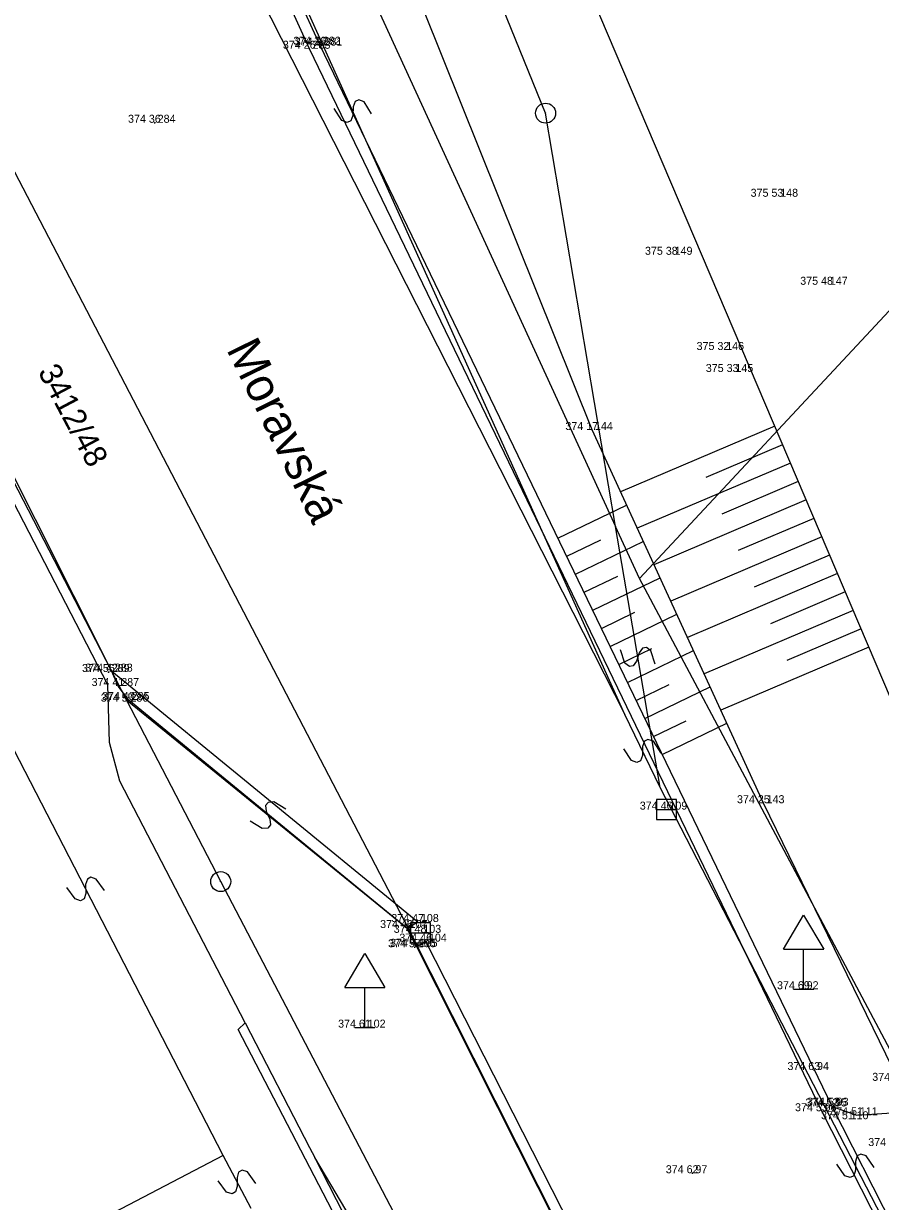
# Model space of a CAD drawing. Extents: x -601196 to -600262, y -1082523 to -1081922.
# Drawn here: x -600485.65 to -600464.23, y -1082316.78 to -1082287.34 of the extents above; entities that cross this region are included whole.
import ezdxf

# ---------------------------------------------------------------- set-up
doc = ezdxf.new("R2010")
doc.units = 0
for name, color, linetype in [('Vrstva 1', 7, 'Continuous'), ('Vrstva 10', 7, 'Continuous'), ('Vrstva 11', 7, 'Continuous'), ('Vrstva 14', 7, 'Continuous'), ('Vrstva 2', 7, 'Continuous'), ('Vrstva 20', 7, 'Continuous'), ('Vrstva 25', 7, 'Continuous'), ('Vrstva 27', 7, 'Continuous'), ('Vrstva 3', 7, 'Continuous'), ('Vrstva 34', 7, 'Continuous'), ('Vrstva 47', 7, 'Continuous')]:
    doc.layers.add(name, color=color, linetype=linetype)

msp = doc.modelspace()

# ---------------------------------------------------------------- linework, layer by layer
at = {"layer": 'Vrstva 1'}
for p, q in [((-600478.5, -1082287.97), (-600478.5, -1082287.97)), ((-600478.24, -1082287.87), (-600478.24, -1082287.87)), ((-600478.2, -1082287.89), (-600478.2, -1082287.89)), ((-600482.37, -1082289.82), (-600482.37, -1082289.82)), ((-600466.81, -1082291.67), (-600466.81, -1082291.67)), ((-600469.45, -1082293.12), (-600469.45, -1082293.12)), ((-600465.57, -1082293.87), (-600465.57, -1082293.87)), ((-600468.16, -1082295.5), (-600468.16, -1082295.5)), ((-600467.93, -1082296.05), (-600467.93, -1082296.05)), ((-600471.44, -1082297.5), (-600471.44, -1082297.5)), ((-600483.52, -1082303.55), (-600483.52, -1082303.55)), ((-600483.44, -1082303.54), (-600483.44, -1082303.54)), ((-600483.28, -1082303.9), (-600483.28, -1082303.9)), ((-600483.02, -1082304.25), (-600483.02, -1082304.25)), ((-600483.05, -1082304.29), (-600483.05, -1082304.29)), ((-600467.15, -1082306.83), (-600467.15, -1082306.83)), ((-600469.58, -1082306.99), (-600469.58, -1082306.99)), ((-600475.79, -1082309.8), (-600475.79, -1082309.8)), ((-600476.07, -1082309.95), (-600476.07, -1082309.95)), ((-600475.73, -1082310.07), (-600475.73, -1082310.07)), ((-600475.87, -1082310.43), (-600475.87, -1082310.43)), ((-600475.82, -1082310.42), (-600475.82, -1082310.42)), ((-600475.59, -1082310.29), (-600475.59, -1082310.29)), ((-600466.15, -1082311.48), (-600466.15, -1082311.48)), ((-600477.12, -1082312.44), (-600477.12, -1082312.44)), ((-600465.89, -1082313.5), (-600465.89, -1082313.5)), ((-600465.7, -1082314.53), (-600465.7, -1082314.53)), ((-600465.44, -1082314.41), (-600465.44, -1082314.41)), ((-600465.4, -1082314.39), (-600465.4, -1082314.39)), ((-600465.05, -1082314.73), (-600465.05, -1082314.73)), ((-600464.82, -1082314.63), (-600464.82, -1082314.63)), ((-600468.93, -1082316.08), (-600468.93, -1082316.08))]:
    msp.add_line(p, q, dxfattribs=at)
at = {"layer": 'Vrstva 10'}
for p, q in [((-600478.24, -1082287.87), (-600482.87, -1082277.7)), ((-600465.44, -1082314.41), (-600478.24, -1082287.87)), ((-600483.44, -1082303.54), (-600486.56, -1082297.33)), ((-600483.28, -1082303.9), (-600483.44, -1082303.54)), ((-600483.02, -1082304.25), (-600483.28, -1082303.9)), ((-600476.07, -1082309.95), (-600483.02, -1082304.25)), ((-600475.82, -1082310.42), (-600476.07, -1082309.95)), ((-600472.22, -1082317.55), (-600475.82, -1082310.42)), ((-600460.01, -1082325.09), (-600465.44, -1082314.41))]:
    msp.add_line(p, q, dxfattribs=at)
at = {"layer": 'Vrstva 11'}
for p, q in [((-600478.5, -1082287.97), (-600483.06, -1082277.86)), ((-600465.7, -1082314.53), (-600478.5, -1082287.97)), ((-600475.79, -1082309.8), (-600483.44, -1082303.54)), ((-600476.07, -1082309.95), (-600475.79, -1082309.8)), ((-600475.59, -1082310.29), (-600475.82, -1082310.42)), ((-600471.95, -1082317.45), (-600475.59, -1082310.29)), ((-600460.25, -1082325.17), (-600465.7, -1082314.53)), ((-600465.44, -1082314.41), (-600464.82, -1082314.63)), ((-600464.82, -1082314.63), (-600462.97, -1082314.5))]:
    msp.add_line(p, q, dxfattribs=at)
at = {"layer": 'Vrstva 14'}
for p, q in [((-600463.33, -1082305.73), (-600472.01, -1082285.33)), ((-600471.44, -1082297.5), (-600475.64, -1082287.01)), ((-600467.15, -1082306.83), (-600471.44, -1082297.5)), ((-600463.77, -1082313.77), (-600467.15, -1082306.83))]:
    msp.add_line(p, q, dxfattribs=at)
at = {"layer": 'Vrstva 20'}
for p, q in [((-600478.21, -1082287.89), (-600478.19, -1082287.89)), ((-600478.2, -1082287.875), (-600478.2, -1082287.89)), ((-600478.2, -1082287.905), (-600478.2, -1082287.89)), ((-600482.38, -1082289.82), (-600482.36, -1082289.82)), ((-600482.37, -1082289.805), (-600482.37, -1082289.82)), ((-600482.37, -1082289.835), (-600482.37, -1082289.82)), ((-600483.53, -1082303.55), (-600483.51, -1082303.55)), ((-600483.52, -1082303.535), (-600483.52, -1082303.55)), ((-600483.52, -1082303.565), (-600483.52, -1082303.55)), ((-600483.06, -1082304.29), (-600483.04, -1082304.29)), ((-600483.05, -1082304.275), (-600483.05, -1082304.29)), ((-600483.05, -1082304.305), (-600483.05, -1082304.29)), ((-600475.88, -1082310.43), (-600475.86, -1082310.43)), ((-600475.87, -1082310.415), (-600475.87, -1082310.43)), ((-600475.87, -1082310.445), (-600475.87, -1082310.43)), ((-600465.9, -1082313.5), (-600465.88, -1082313.5)), ((-600465.89, -1082313.485), (-600465.89, -1082313.5)), ((-600465.89, -1082313.515), (-600465.89, -1082313.5)), ((-600465.41, -1082314.39), (-600465.39, -1082314.39)), ((-600465.4, -1082314.375), (-600465.4, -1082314.39)), ((-600465.4, -1082314.405), (-600465.4, -1082314.39)), ((-600468.94, -1082316.08), (-600468.92, -1082316.08)), ((-600468.93, -1082316.065), (-600468.93, -1082316.08)), ((-600468.93, -1082316.095), (-600468.93, -1082316.08))]:
    msp.add_line(p, q, dxfattribs=at)
at = {"layer": 'Vrstva 25'}
for p, q in [((-600466.871, -1082297.408), (-600470.728, -1082299.049)), ((-600466.675, -1082297.868), (-600468.597, -1082298.686)), ((-600466.479, -1082298.328), (-600470.31, -1082299.958)), ((-600466.284, -1082298.788), (-600468.192, -1082299.601)), ((-600466.088, -1082299.249), (-600469.892, -1082300.867)), ((-600472.29, -1082300.207), (-600470.575, -1082299.38)), ((-600465.892, -1082299.709), (-600467.787, -1082300.515)), ((-600472.073, -1082300.657), (-600471.22, -1082300.246)), ((-600471.856, -1082301.108), (-600470.158, -1082300.289)), ((-600465.696, -1082300.169), (-600469.474, -1082301.776)), ((-600465.501, -1082300.629), (-600467.383, -1082301.43)), ((-600471.638, -1082301.558), (-600470.794, -1082301.151)), ((-600471.421, -1082302.008), (-600469.74, -1082301.198)), ((-600465.305, -1082301.089), (-600469.056, -1082302.685)), ((-600465.109, -1082301.549), (-600466.978, -1082302.344)), ((-600471.204, -1082302.459), (-600470.367, -1082302.055)), ((-600470.987, -1082302.909), (-600469.322, -1082302.106)), ((-600464.913, -1082302.009), (-600468.638, -1082303.594)), ((-600464.717, -1082302.469), (-600466.573, -1082303.259)), ((-600470.77, -1082303.359), (-600469.941, -1082302.96)), ((-600470.552, -1082303.81), (-600468.904, -1082303.015)), ((-600464.522, -1082302.929), (-600468.22, -1082304.503)), ((-600470.335, -1082304.26), (-600469.515, -1082303.865)), ((-600470.118, -1082304.71), (-600468.486, -1082303.924)), ((-600469.901, -1082305.161), (-600469.089, -1082304.769)), ((-600469.684, -1082305.611), (-600468.069, -1082304.832))]:
    msp.add_line(p, q, dxfattribs=at)
at = {"layer": 'Vrstva 27'}
for p, q in [((-600469.83, -1082306.99), (-600469.33, -1082306.99)), ((-600475.98, -1082310.07), (-600475.48, -1082310.07))]:
    msp.add_line(p, q, dxfattribs=at)
for points in [[(-600469.83, -1082307.24), (-600469.33, -1082307.24), (-600469.33, -1082306.74), (-600469.83, -1082306.74)], [(-600475.98, -1082310.32), (-600475.48, -1082310.32), (-600475.48, -1082309.82), (-600475.98, -1082309.82)]]:
    msp.add_lwpolyline(points, close=True, dxfattribs=at)
at = {"layer": 'Vrstva 34'}
for p, q in [((-600466.65, -1082310.48), (-600466.15, -1082309.63)), ((-600466.15, -1082309.63), (-600465.65, -1082310.48)), ((-600477.62, -1082311.44), (-600477.12, -1082310.59)), ((-600477.12, -1082310.59), (-600476.62, -1082311.44)), ((-600466.65, -1082310.48), (-600465.65, -1082310.48)), ((-600466.15, -1082311.48), (-600466.15, -1082310.48)), ((-600477.62, -1082311.44), (-600476.62, -1082311.44)), ((-600477.12, -1082312.44), (-600477.12, -1082311.44)), ((-600466.4, -1082311.48), (-600465.9, -1082311.48)), ((-600477.37, -1082312.44), (-600476.87, -1082312.44))]:
    msp.add_line(p, q, dxfattribs=at)
at = {"layer": 'Vrstva 47'}
for p, q in [((-600509.18, -1082228.7), (-600470.62, -1082304.61)), ((-600496.18, -1082271.26), (-600476.01, -1082310)), ((-600470.62, -1082304.61), (-600484.21, -1082274.45)), ((-600472.6, -1082289.58), (-600475.82, -1082281.64)), ((-600477.94, -1082284.47), (-600470.85, -1082299.91)), ((-600483.07, -1082304.26), (-600493.08, -1082284.9)), ((-600483.54, -1082303.87), (-600492.72, -1082286.11)), ((-600477.269, -1082289.244), (-600477.36, -1082289.286)), ((-600477.136, -1082289.295), (-600477.269, -1082289.244)), ((-600477.693, -1082289.764), (-600477.882, -1082289.466)), ((-600477.41, -1082289.418), (-600477.419, -1082289.641)), ((-600477.36, -1082289.286), (-600477.41, -1082289.418)), ((-600476.947, -1082289.593), (-600477.136, -1082289.295)), ((-600477.56, -1082289.815), (-600477.693, -1082289.764)), ((-600477.469, -1082289.773), (-600477.56, -1082289.815)), ((-600477.419, -1082289.641), (-600477.469, -1082289.773)), ((-600470.85, -1082299.91), (-600472.6, -1082289.58)), ((-600470.25, -1082301.21), (-600463.9, -1082294.4)), ((-600469.74, -1082306.44), (-600470.85, -1082299.91)), ((-600470.25, -1082301.21), (-600470.85, -1082299.91)), ((-600458.32, -1082323.68), (-600470.25, -1082301.21)), ((-600480.66, -1082315.64), (-600487.53, -1082302.31)), ((-600470.623, -1082303.332), (-600470.731, -1082302.995)), ((-600470.262, -1082303.068), (-600470.327, -1082303.281)), ((-600470.18, -1082302.952), (-600470.262, -1082303.068)), ((-600470.082, -1082302.935), (-600470.18, -1082302.952)), ((-600469.966, -1082303.017), (-600470.082, -1082302.935)), ((-600469.858, -1082303.354), (-600469.966, -1082303.017)), ((-600470.507, -1082303.414), (-600470.623, -1082303.332)), ((-600470.327, -1082303.281), (-600470.409, -1082303.397)), ((-600470.409, -1082303.397), (-600470.507, -1082303.414)), ((-600483.5, -1082305.31), (-600483.54, -1082303.87)), ((-600476.01, -1082310), (-600483.07, -1082304.26)), ((-600480.72, -1082308.79), (-600483.07, -1082304.26)), ((-600469.74, -1082306.44), (-600470.62, -1082304.61)), ((-600483.24, -1082306.28), (-600483.5, -1082305.31)), ((-600470.178, -1082305.413), (-600470.181, -1082305.636)), ((-600470.131, -1082305.279), (-600470.178, -1082305.413)), ((-600470.041, -1082305.236), (-600470.131, -1082305.279)), ((-600469.907, -1082305.283), (-600470.041, -1082305.236)), ((-600469.711, -1082305.576), (-600469.907, -1082305.283)), ((-600470.452, -1082305.766), (-600470.648, -1082305.473)), ((-600470.181, -1082305.636), (-600470.228, -1082305.77)), ((-600470.318, -1082305.813), (-600470.452, -1082305.766)), ((-600470.228, -1082305.77), (-600470.318, -1082305.813)), ((-600480.11, -1082312.32), (-600483.24, -1082306.28)), ((-600459.97, -1082325.35), (-600469.74, -1082306.44)), ((-600479.537, -1082306.809), (-600479.6, -1082306.887)), ((-600479.6, -1082306.887), (-600479.586, -1082307.028)), ((-600479.396, -1082306.795), (-600479.537, -1082306.809)), ((-600479.093, -1082306.977), (-600479.396, -1082306.795)), ((-600479.586, -1082307.028), (-600479.493, -1082307.231)), ((-600479.683, -1082307.464), (-600479.986, -1082307.282)), ((-600479.542, -1082307.45), (-600479.683, -1082307.464)), ((-600479.479, -1082307.372), (-600479.542, -1082307.45)), ((-600479.493, -1082307.231), (-600479.479, -1082307.372)), ((-600483.964, -1082308.682), (-600484.053, -1082308.728)), ((-600483.829, -1082308.725), (-600483.964, -1082308.682)), ((-600484.36, -1082309.224), (-600484.565, -1082308.936)), ((-600484.053, -1082308.728), (-600484.096, -1082308.863)), ((-600484.096, -1082308.863), (-600484.093, -1082309.086)), ((-600483.624, -1082309.013), (-600483.829, -1082308.725)), ((-600468.05, -1082332.99), (-600480.72, -1082308.79)), ((-600484.225, -1082309.267), (-600484.36, -1082309.224)), ((-600484.136, -1082309.221), (-600484.225, -1082309.267)), ((-600484.093, -1082309.086), (-600484.136, -1082309.221)), ((-600476.01, -1082310), (-600469.24, -1082323.45)), ((-600480.28, -1082312.49), (-600480.11, -1082312.32)), ((-600458.72, -1082354.01), (-600480.28, -1082312.49)), ((-600480.11, -1082312.32), (-600478.5, -1082315.44)), ((-600478.5, -1082315.44), (-600478.37, -1082315.69)), ((-600480.66, -1082315.64), (-600484.27, -1082317.52)), ((-600479.96, -1082316.96), (-600480.66, -1082315.64)), ((-600468.28, -1082335.2), (-600478.37, -1082315.69)), ((-600468.05, -1082332.99), (-600478.37, -1082315.69)), ((-600464.813, -1082315.648), (-600464.856, -1082315.783)), ((-600464.724, -1082315.602), (-600464.813, -1082315.648)), ((-600464.589, -1082315.645), (-600464.724, -1082315.602)), ((-600464.384, -1082315.933), (-600464.589, -1082315.645)), ((-600480.182, -1082316.006), (-600480.271, -1082316.053)), ((-600480.047, -1082316.047), (-600480.182, -1082316.006)), ((-600479.839, -1082316.333), (-600480.047, -1082316.047)), ((-600465.12, -1082316.144), (-600465.325, -1082315.856)), ((-600464.853, -1082316.006), (-600464.896, -1082316.141)), ((-600464.856, -1082315.783), (-600464.853, -1082316.006)), ((-600480.572, -1082316.552), (-600480.78, -1082316.266)), ((-600480.271, -1082316.053), (-600480.312, -1082316.188)), ((-600480.312, -1082316.188), (-600480.307, -1082316.411)), ((-600464.985, -1082316.187), (-600465.12, -1082316.144)), ((-600464.896, -1082316.141), (-600464.985, -1082316.187)), ((-600480.437, -1082316.593), (-600480.572, -1082316.552)), ((-600480.348, -1082316.546), (-600480.437, -1082316.593)), ((-600480.307, -1082316.411), (-600480.348, -1082316.546))]:
    msp.add_line(p, q, dxfattribs=at)
for centre, radius in [((-600472.6, -1082289.58), 0.25), ((-600472.6, -1082289.58), 0.005), ((-600480.72, -1082308.79), 0.25), ((-600480.72, -1082308.79), 0.005)]:
    msp.add_circle(centre, radius, dxfattribs=at)

# ---------------------------------------------------------------- texts
at = {"layer": 'Vrstva 2'}
for s, p in [(' 283', (-600478.5, -1082287.97)), (' 282', (-600478.24, -1082287.87)), (' 281', (-600478.2, -1082287.89)), (' 284', (-600482.37, -1082289.82)), (' 148', (-600466.81, -1082291.67)), (' 149', (-600469.45, -1082293.12)), (' 147', (-600465.57, -1082293.87)), (' 146', (-600468.16, -1082295.5)), (' 145', (-600467.93, -1082296.05)), (' 144', (-600471.44, -1082297.5)), (' 289', (-600483.52, -1082303.55)), (' 288', (-600483.44, -1082303.54)), (' 287', (-600483.28, -1082303.9)), (' 286', (-600483.05, -1082304.29)), (' 285', (-600483.02, -1082304.25)), (' 109', (-600469.58, -1082306.99)), (' 143', (-600467.15, -1082306.83)), (' 107', (-600476.07, -1082309.95)), (' 108', (-600475.79, -1082309.8)), (' 103', (-600475.73, -1082310.07)), (' 104', (-600475.59, -1082310.29)), (' 106', (-600475.87, -1082310.43)), (' 105', (-600475.82, -1082310.42)), (' 92', (-600466.15, -1082311.48)), (' 102', (-600477.12, -1082312.44)), (' 94', (-600465.89, -1082313.5)), (' 95', (-600465.44, -1082314.41)), (' 93', (-600465.4, -1082314.39)), (' 96', (-600465.7, -1082314.53)), (' 110', (-600465.05, -1082314.73)), (' 111', (-600464.82, -1082314.63)), (' 97', (-600468.93, -1082316.08))]:
    msp.add_text(s, height=0.2, dxfattribs=at).set_placement(p)
at = {"layer": 'Vrstva 3'}
for s, p in [('374 26 ', (-600479.166, -1082287.97)), ('374 26 ', (-600478.906, -1082287.87)), ('374 37 ', (-600478.866, -1082287.89)), ('374 36 ', (-600483.036, -1082289.82)), ('375 53 ', (-600467.476, -1082291.67)), ('375 38 ', (-600470.116, -1082293.12)), ('375 48 ', (-600466.236, -1082293.87)), ('375 32 ', (-600468.826, -1082295.5)), ('375 33 ', (-600468.596, -1082296.05)), ('374 17 ', (-600472.106, -1082297.5)), ('374 56 ', (-600484.186, -1082303.55)), ('374 42 ', (-600484.106, -1082303.54)), ('374 41 ', (-600483.946, -1082303.9)), ('374 55 ', (-600483.716, -1082304.29)), ('374 43 ', (-600483.686, -1082304.25)), ('374 46 ', (-600470.246, -1082306.99)), ('374 25 ', (-600467.816, -1082306.83)), ('374 46 ', (-600476.736, -1082309.95)), ('374 47 ', (-600476.456, -1082309.8)), ('374 48 ', (-600476.396, -1082310.07)), ('374 46 ', (-600476.256, -1082310.29)), ('374 57 ', (-600476.536, -1082310.43)), ('374 44 ', (-600476.486, -1082310.42)), ('374 69 ', (-600466.816, -1082311.48)), ('374 61 ', (-600477.786, -1082312.44)), ('374 63 ', (-600466.556, -1082313.5)), ('374 31 ', (-600464.436, -1082313.77)), ('374 52 ', (-600466.106, -1082314.41)), ('374 53 ', (-600466.066, -1082314.39)), ('374 53 ', (-600466.366, -1082314.53)), ('374 51 ', (-600465.716, -1082314.73)), ('374 51 ', (-600465.486, -1082314.63)), ('374 48 ', (-600464.536, -1082315.4)), ('374 62 ', (-600469.596, -1082316.08))]:
    msp.add_text(s, height=0.2, dxfattribs=at).set_placement(p)
at = {"layer": 'Vrstva 47'}
for s, height, rotation, p in [('Moravská', 0.85, 296.242, (-600480.589, -1082295.479)), ('3412/48', 0.57, 297.8824, (-600485.299, -1082296.042))]:
    msp.add_text(s, height=height, rotation=rotation, dxfattribs=at).set_placement(p)

doc.saveas('drawing.dxf')
